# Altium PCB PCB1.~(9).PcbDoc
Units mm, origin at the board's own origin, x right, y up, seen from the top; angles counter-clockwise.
Board outline 91.95 x 31.11 mm, 2 copper layers (Top Layer, Bottom Layer); 13 components, 12 nets, 39 pads, 0 vias.
Unrouted connection lines stored in the file: 17.
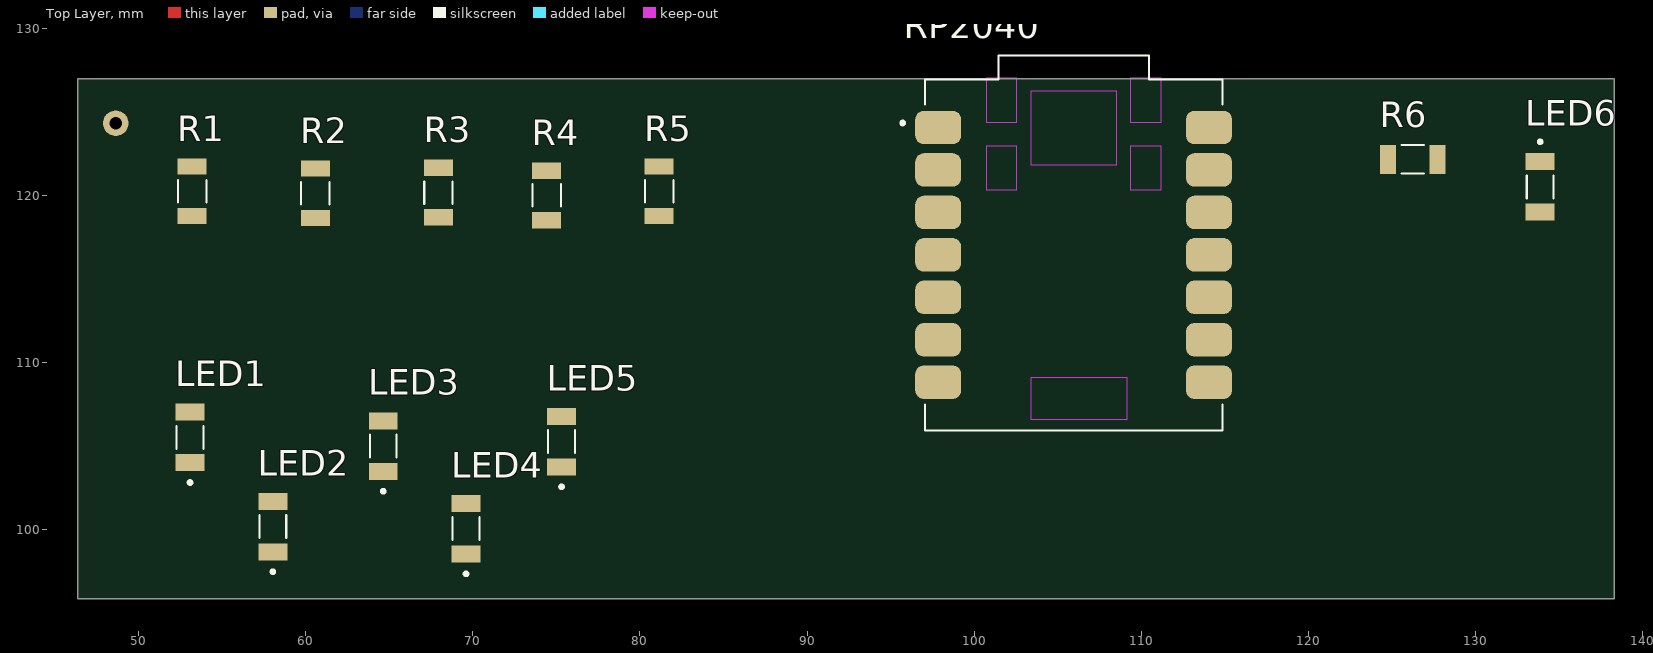
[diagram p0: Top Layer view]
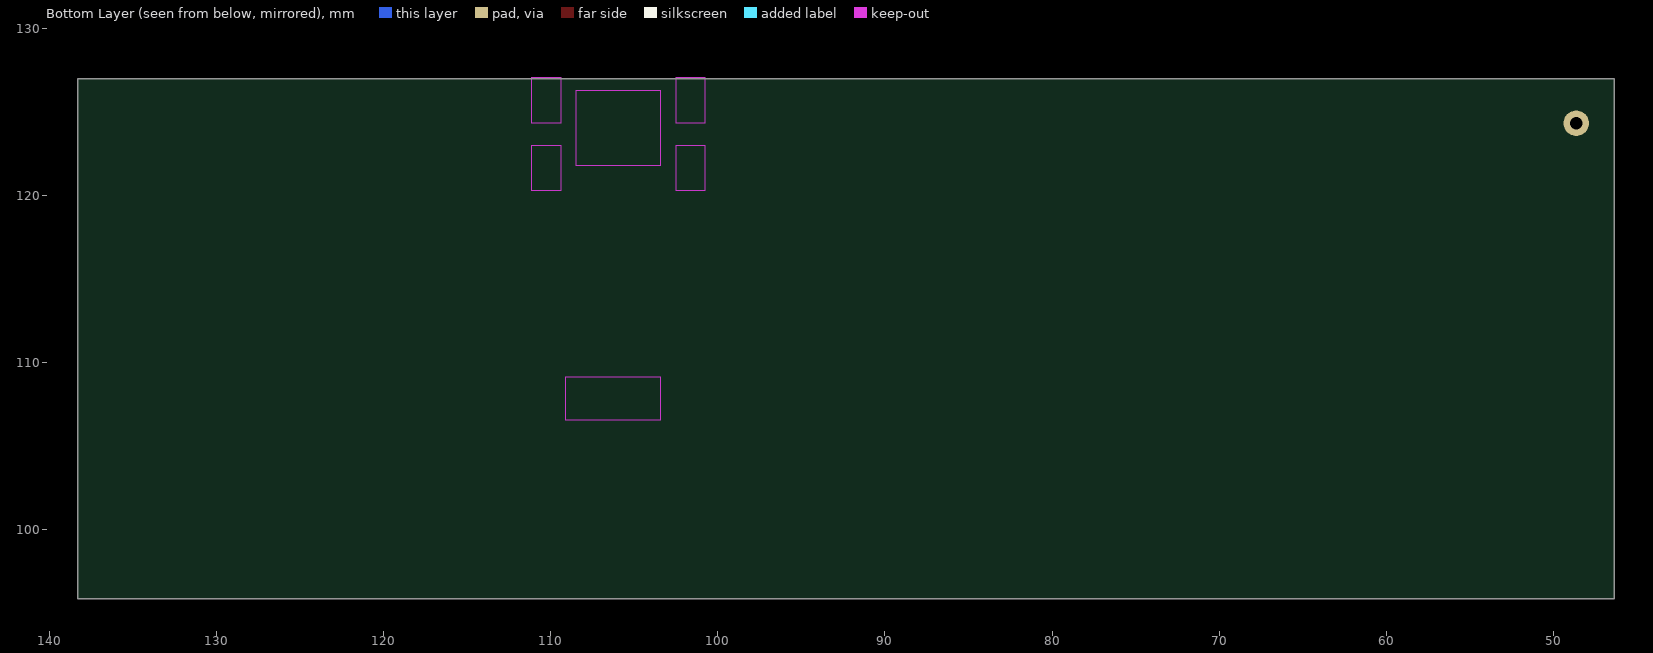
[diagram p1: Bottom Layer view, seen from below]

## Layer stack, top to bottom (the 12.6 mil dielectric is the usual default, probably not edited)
Top Solder: solder mask 0.0102, Solder Resist, Dk 3.5
Top Layer: signal copper 0.0356
Dielectric 1: dielectric 0.32, FR-4, Dk 4.8
Bottom Layer: signal copper 0.0356
Bottom Solder: solder mask 0.0102, Solder Resist, Dk 3.5

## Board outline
46.355,95.885 138.303,95.885 138.303,127 46.355,127

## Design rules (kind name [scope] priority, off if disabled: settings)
Clearance [All] p1: gap=0.254 ignorepadtopadclearanceinfootprint=FALSE except(0: Arc-Hole Track-Hole SMDPad-Hole THPad-Hole Via-Hole Fill-Hole Poly-Hole Region-Hole Text-Hole)
PolygonConnect [All] p1: connectstyle=Relief reliefconductorwidth=0.254 reliefentries=4 polygonreliefangle="90 Angle" airgapwidth=0.254
RoutingVias [All] p1: holewidth=0.711 width=1.27 viastyle="Through Hole" minholewidth=0.711 minwidth=1.27 maxholewidth=0.711 maxwidth=1.27
SolderMaskExpansion [All] p1: expansion=0.102 istentingtop=FALSE
Width [All] p1: maxlimit=0.254 minlimit=0.254 preferedwidth=0.254
30 further rules are at their usual default settings.

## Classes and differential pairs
component class XIAO_Schem: LED1 LED3 LED4 LED5 LED6 R1 R2 R3 R4 R5 R6 RP2040

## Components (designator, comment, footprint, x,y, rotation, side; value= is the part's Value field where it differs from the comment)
LED1 "LHN974_RED_LED_1206" LED2 53.086,105.537 r90 top
LED2 "LHN974_RED_LED_1206" LED2 58.039,100.203 r90 top
LED3 "LHN974_RED_LED_1206" LED2 64.643,105.015 r90 top
LED4 "LHN974_RED_LED_1206" LED2 69.596,100.076 r90 top
LED5 "LHN974_RED_LED_1206" LED2 75.311,105.283 r90 top
LED6 "LHN974_RED_LED_1206" LED2 133.858,120.523 r270 top
R1 "1k" 1k 53.213,120.269 r90 top
R2 "1k" 1k 60.579,120.142 r90 top
R3 "1k" 1k 67.945,120.186 r90 top
R4 "1k" 1k 74.422,120.015 r90 top
R5 "1k" 1k 81.153,120.269 r90 top
R6 "1k" 1k 126.238,122.174 r0 top
RP2040 "102010428" 102010428 105.946,116.459 r0 top

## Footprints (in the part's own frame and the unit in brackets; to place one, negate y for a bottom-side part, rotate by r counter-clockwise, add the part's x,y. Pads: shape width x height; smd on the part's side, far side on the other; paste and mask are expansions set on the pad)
1k [mm]
  rect 0.97x1.73 smd: 1(-1.48,0) 2(1.48,0)
  silkscreen extent -0.67,-0.85 0.67,0.85, body extent -1.55,-0.8 1.55,0.8, height 0.65
102010428 [mm]
  rrect50% 2.75x2 smd: 1(-8.1,7.62) 2(-8.1,5.08) 3(-8.1,2.54) 4(-8.1,0) 5(-8.1,-2.54) 6(-8.1,-5.08) 7(-8.1,-7.62) 8(8.1,-7.62) 9(8.1,-5.08) 10(8.1,-2.54) 11(8.1,0) 12(8.1,2.54) 13(8.1,5.08) 14(8.1,7.62)
  Keep-Out Layer region: 2.54,5.375 -2.54,5.375 -2.54,9.82 2.54,9.82
  Keep-Out Layer region: 5.207,7.915 3.429,7.915 3.429,10.582 5.207,10.582
  Keep-Out Layer region: 5.207,3.851 3.429,3.851 3.429,6.518 5.207,6.518
  Keep-Out Layer region: -3.429,3.851 -5.207,3.851 -5.207,6.518 -3.429,6.518
  Keep-Out Layer region: -3.429,7.915 -5.207,7.915 -5.207,10.582 -3.429,10.582
  Keep-Out Layer region: 3.175,-9.865 -2.54,-9.865 -2.54,-7.325 3.175,-7.325
  silkscreen extent -10.33,-10.5 8.9,11.92, body extent -8.75,-10.5 8.75,11.5, height 4.41
LED2 [mm] "LEDC3216X120N"
  rect 1.01x1.73 smd: NEG(1.51,0) POS(-1.51,0)
  silkscreen extent -2.8,-0.8 0.68,0.8, body extent -1.6,-0.8 1.6,0.8, height 1.2

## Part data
LED1 LED2 LED3 LED4 LED5 LED6: library part LED2, "2.6 V Red LED SMD", Package=None
R1 R2 R3 R4 R5 R6: "Res Thick Film 3.2 x 1.6 mm 6.8K Ohm 1% 0.25W(1/4W) 100ppm/ C Molded SMD Paper T/R", Package=None
RP2040: "RP2040 XIAO RP2040 series ARMÂ® CortexÂ®-M0+ MCU 32-Bit Embedded Evaluation Board", Package=None

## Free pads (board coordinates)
  round 1.524 hole 0.762: 7(48.641,124.333)

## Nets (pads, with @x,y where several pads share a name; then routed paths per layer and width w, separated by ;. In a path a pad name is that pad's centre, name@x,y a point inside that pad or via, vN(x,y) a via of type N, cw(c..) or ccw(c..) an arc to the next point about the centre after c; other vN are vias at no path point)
GND: LED1.NEG LED2.NEG LED3.NEG LED4.NEG LED5.NEG LED6.NEG RP2040.13
NetLED1_POS: LED1.POS R1.1
NetLED2_POS: LED2.POS R2.1
NetLED3_POS: LED3.POS R3.1
NetLED4_POS: LED4.POS R4.1
NetLED5_POS: LED5.POS R5.1
NetLED6_POS: LED6.POS R6.2
NetR1_2: R1.2 RP2040.1
NetR2_2: R2.2 RP2040.2
NetR3_2: R3.2 RP2040.3
NetR4_2: R4.2 RP2040.4
NetR5_2: R5.2 RP2040.5
pads on no net: R6.1 RP2040.6 RP2040.7 RP2040.8 RP2040.9 RP2040.10 RP2040.11 RP2040.12 RP2040.14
